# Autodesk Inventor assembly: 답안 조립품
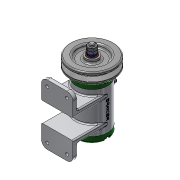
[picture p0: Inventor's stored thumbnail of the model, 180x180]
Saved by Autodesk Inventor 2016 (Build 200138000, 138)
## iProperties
Created: 2017-02
Part Number: 답안 조립품
Material: 일반
Document SubType Name: Assembly
Designer: H
Author: H
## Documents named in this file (16)
- C:\Users\CAMTIC\Desktop\470207V1006\답안 조립품.iam
- C:\Users\CAMTIC\Desktop\470207V1006\본체.ipt
- C:\Users\CAMTIC\Desktop\470207V1006\V벨트풀리.ipt
- C:\Users\CAMTIC\Desktop\470207V1006\너트 M 8.ipt
- C:\Users\CAMTIC\Desktop\470207V1006\니플 M 6 x 0.75.ipt
- C:\Users\CAMTIC\Desktop\470207V1006\뒤커버.ipt
- C:\Users\CAMTIC\Desktop\470207V1006\베어링 15 x 32 x 9.ipt
- C:\Users\CAMTIC\Desktop\470207V1006\볼트 M 6 x 8.ipt
- C:\Users\CAMTIC\Desktop\470207V1006\볼트 M4 x 12.ipt
- C:\Users\CAMTIC\Desktop\470207V1006\스프링와셔 8.ipt
- C:\Users\CAMTIC\Desktop\470207V1006\앞커버.ipt
- C:\Users\CAMTIC\Desktop\470207V1006\오일 실 15 25 7.ipt
- C:\Users\CAMTIC\Desktop\470207V1006\와셔 6x11.5.ipt
- C:\Users\CAMTIC\Desktop\470207V1006\와셔 8x17.ipt
- C:\Users\CAMTIC\Desktop\470207V1006\축.ipt
- C:\Users\CAMTIC\Desktop\470207V1006\키 3 x 3 x 12.ipt
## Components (11 placed, 3 different names)
1. V벨트풀리:1
2. KS B 2023 6002 - 15 x 32 x 9:1
3. KS B 2023 6002 - 15 x 32 x 9:2
4. ISO 4762 M4 x 12:2
5. ISO 4762 M4 x 12:3
6. ISO 4762 M4 x 12:4
7. ISO 4762 M4 x 12:5
8. ISO 4762 M4 x 12:1
9. ISO 4762 M4 x 12:6
10. ISO 4762 M4 x 12:7
11. ISO 4762 M4 x 12:8
